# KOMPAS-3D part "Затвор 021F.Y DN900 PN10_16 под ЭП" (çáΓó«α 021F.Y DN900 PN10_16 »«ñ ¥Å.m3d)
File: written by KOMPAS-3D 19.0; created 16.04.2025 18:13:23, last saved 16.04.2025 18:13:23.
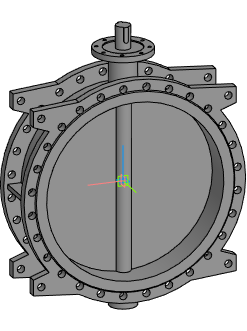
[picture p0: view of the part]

Document properties: Автор: Евгений; Полное имя файла: E:\Dendor Работа Сачек\3D для проекитирвщиков\1.6 Тип 021F.Y Затвор дисковый поворотный фланцевый\stp_Тип 021F.Y Затвор  DN40 PN10_16 под ЭП\Затвор 021F.Y DN900 PN10_16 под ЭП.m3d

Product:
- Part/product: Затвор 021F.Y DN900 PN10_16 под ЭП

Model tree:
1. Операция без истории:1  (labels: Затвор 021F.Y DN900 PN10_16 под ЭП)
